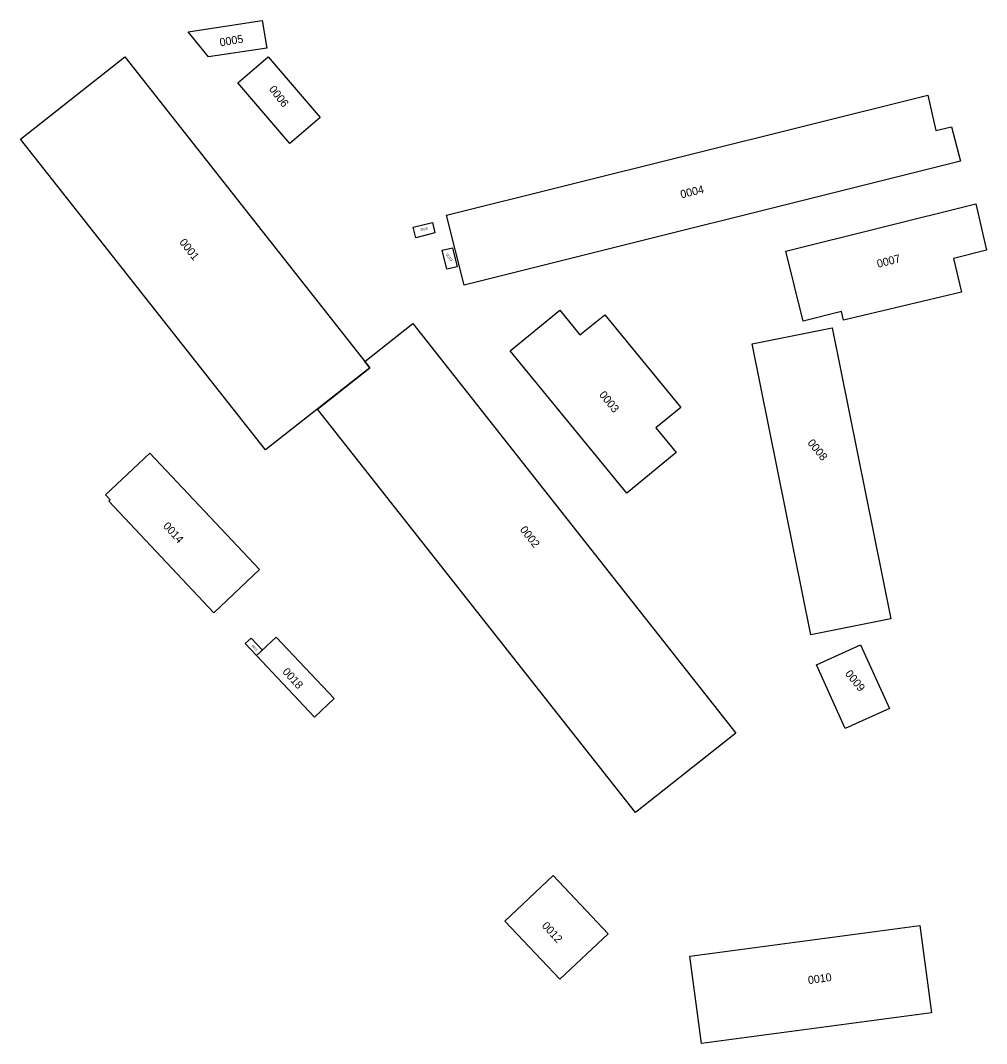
# Model space of a CAD drawing. Extents: x 704383 to 706615, y 7057567 to 7059313.
# Drawn here: x 704711.1 to 704831.9, y 7059184.8 to 7059312.7 of the extents above; entities that cross this region are included whole.
import ezdxf

# ---------------------------------------------------------------- set-up
doc = ezdxf.new("R2010")
doc.units = 0
doc.layers.add('GEOSID_BATI_AERIEN _POLYGONE', color=7, linetype='Continuous')
doc.layers.add('GEOSID_BATI_AERIEN_NUMERO', color=7, linetype='Continuous')

msp = doc.modelspace()

# ---------------------------------------------------------------- linework, layer by layer
at = {"layer": 'GEOSID_BATI_AERIEN _POLYGONE'}
for points in [[(704732.06, 7059311.24), (704741.33, 7059312.67), (704741.91, 7059309.22), (704734.61, 7059308.12)], [(704711.1, 7059297.85), (704724.14, 7059308.13), (704754.79, 7059269.27), (704741.76, 7059258.99)], [(704738.29, 7059304.89), (704742.09, 7059308.14), (704748.59, 7059300.54), (704744.79, 7059297.29)], [(704764.38, 7059288.32), (704824.53, 7059303.35), (704825.56, 7059298.9), (704827.5, 7059299.38), (704828.65, 7059295.1), (704766.56, 7059279.59)], [(704806.78, 7059283.82), (704830.56, 7059289.76), (704831.89, 7059283.97), (704827.75, 7059282.94), (704828.75, 7059278.72), (704814, 7059275.23), (704813.76, 7059276.3), (704808.97, 7059275.09)], [(704760.22, 7059286.82), (704762.6, 7059287.41), (704762.92, 7059286.12), (704760.54, 7059285.52)], [(704763.83, 7059283.95), (704765.12, 7059284.27), (704765.72, 7059281.89), (704764.43, 7059281.57)], [(704772.33, 7059271.39), (704778.52, 7059276.46), (704781.05, 7059273.37), (704784.15, 7059275.9), (704793.66, 7059264.3), (704790.56, 7059261.77), (704793.1, 7059258.67), (704786.91, 7059253.6)], [(704748.24, 7059264.09), (704754.8, 7059269.27), (704754.18, 7059270.06), (704760.18, 7059274.79), (704800.56, 7059223.61), (704788, 7059213.7)], [(704802.58, 7059272.25), (704812.6, 7059274.26), (704819.92, 7059237.89), (704809.91, 7059235.87)], [(704721.73, 7059253.37), (704727.28, 7059258.61), (704741.01, 7059244.06), (704735.29, 7059238.66), (704722.15, 7059252.59), (704722.31, 7059252.75)], [(704739.21, 7059234.8), (704739.93, 7059235.49), (704741.35, 7059233.98), (704740.63, 7059233.29)], [(704740.63, 7059233.29), (704743.08, 7059235.6), (704750.32, 7059227.93), (704747.87, 7059225.62)], [(704810.61, 7059232.16), (704816.14, 7059234.66), (704819.75, 7059226.67), (704814.22, 7059224.17)], [(704771.66, 7059200.11), (704777.7, 7059205.82), (704784.57, 7059198.54), (704778.52, 7059192.84)], [(704796.27, 7059184.81), (704794.8, 7059195.72), (704823.55, 7059199.57), (704825.01, 7059188.67)]]:
    msp.add_lwpolyline(points, close=True, dxfattribs=at)

# ---------------------------------------------------------------- texts
at = {"layer": 'GEOSID_BATI_AERIEN_NUMERO'}
for s, height, rotation, p in [('0005', 1, 9.3307, (704736.09, 7059309.43)), ('0006', 1, 307.9879, (704742.11, 7059304.06)), ('0004', 1, 13.5243, (704793.74, 7059290.43)), ('0020', 0.295, 8.0308, (704761.13, 7059286.38)), ('0001', 1, 308.2727, (704730.91, 7059284.93)), ('0019', 0.346, 308.0308, (704764.24, 7059283.38)), ('0007', 1, 14.5051, (704818.33, 7059281.75)), ('0003', 1, 309.3307, (704783.39, 7059265.86)), ('0008', 1, 309.3307, (704809.44, 7059259.85)), ('0014', 1, 312.5129, (704728.86, 7059249.43)), ('0002', 1, 308.2727, (704773.49, 7059249.01)), ('0013', 0.279, 312.5129, (704739.98, 7059234.5)), ('0018', 1, 312.5129, (704743.79, 7059231.22)), ('0009', 1, 309.3307, (704814.14, 7059231)), ('0012', 1, 312.5129, (704776.22, 7059199.48)), ('0010', 1, 8.0003, (704809.63, 7059192.23))]:
    msp.add_text(s, height=height, rotation=rotation, dxfattribs=at).set_placement(p)

doc.saveas('drawing.dxf')
